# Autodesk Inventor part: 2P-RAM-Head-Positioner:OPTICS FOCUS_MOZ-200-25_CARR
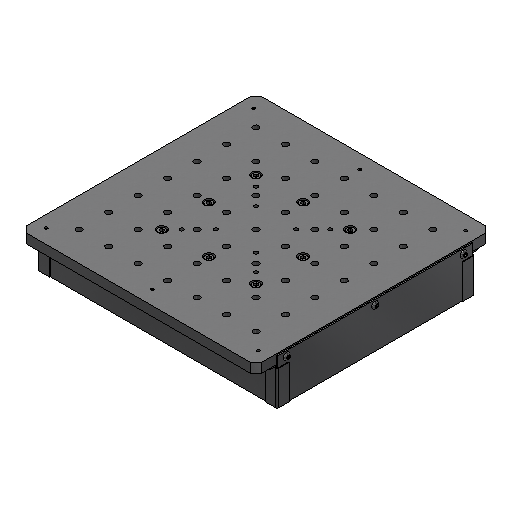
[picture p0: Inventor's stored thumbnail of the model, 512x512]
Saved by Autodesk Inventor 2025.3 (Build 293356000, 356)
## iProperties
RuleStatus: InUse
AfterDocSave0: file://Part Number Cleaner
Created: 2019-09
Material: Generic
Vendor: HHMI: JRC - ID&F
Document SubType Name: Modeling
Designer: arnoldj
Density: 1 g/cm^3
Appearance: Honed - Dark Gray
DESIGN DEPARTMENT: HHMI: JRC - ID&F
ALTERED ITEM PART NUMBER: N/A
ALTERED ITEM VENDOR: N/A
ALTERED ITEM DESCRIPTION: N/A
Author: arnoldj
Revision Number: 0
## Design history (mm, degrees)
feature "NONE:3"
feature "NONE:37"
feature "NONE:55"
feature "NONE:56"
feature "NONE:57"
feature "NONE:58"
feature "NONE:59"
feature "NONE:60"
feature "NONE:61"
feature "NONE:62"
feature "NONE:65"
feature "NONE:66"
feature "NONE:67"
feature "NONE:68"
feature "NONE:70"
feature "NONE:71"
feature "NONE:72"
feature "NONE:73"
feature "NONE:74"
feature "NONE:75"
feature "NONE:76"
feature "NONE:77"
feature "NONE:78"
feature "NONE:79"
feature "NONE:80"
feature "NONE:81"
feature "NONE:82"
feature "NONE:83"
feature "NONE:84"
feature "NONE:85"
feature "NONE:86"
feature "NONE:87"
feature "NONE:88"
feature "NONE:89"
feature "NONE:90"
feature "NONE:91"
body "Srf4"
body "Srf38"
body "Srf56"
body "Srf57"
body "Srf58"
body "Srf59"
body "Srf60"
body "Srf61"
body "Srf62"
body "Srf63"
body "Srf66"
body "Srf67"
body "Srf68"
body "Srf69"
body "Srf71"
body "Srf72"
body "Srf73"
body "Srf74"
body "Srf75"
body "Srf76"
body "Srf77"
body "Srf78"
body "Srf79"
body "Srf80"
body "Srf81"
body "Srf82"
body "Srf83"
body "Srf84"
body "Srf85"
body "Srf86"
body "Srf87"
body "Srf88"
body "Srf89"
body "Srf90"
body "Srf91"
body "Srf92"
